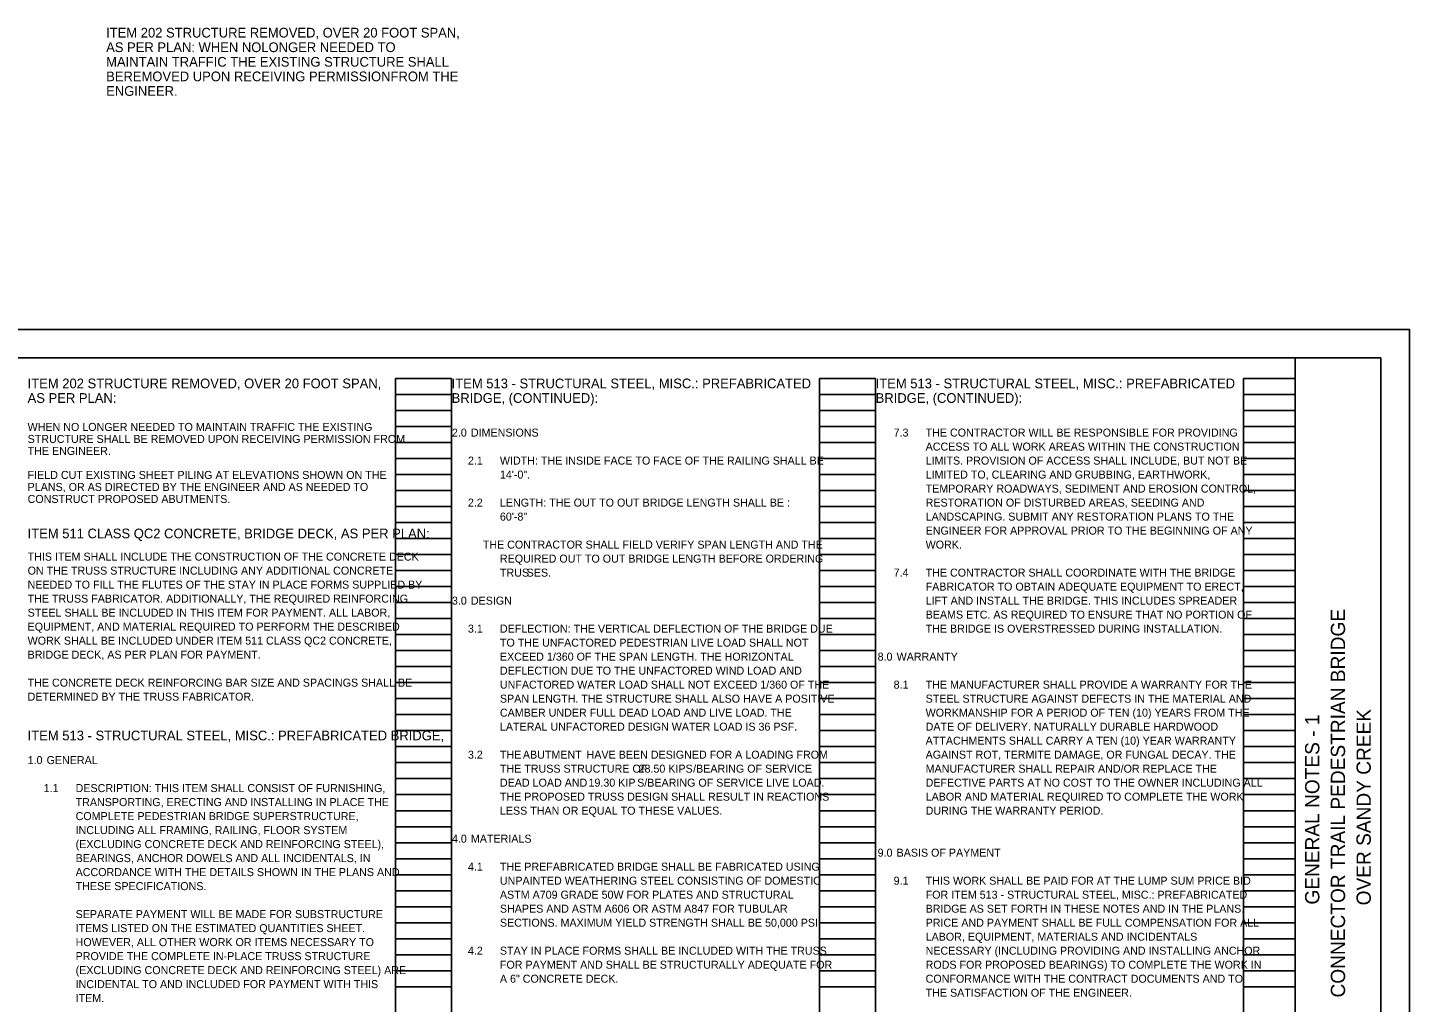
# Model space of a CAD drawing. Extents: x -14.3 to 34, y -8.8 to 27.3.
# Drawn here: x 9.82 to 34, y 10.23 to 27.28 of the extents above; entities that cross this region are included whole.
import ezdxf

# ---------------------------------------------------------------- set-up
doc = ezdxf.new("R2010")
doc.units = 0
for name, color, linetype in [('BR_P_Gen_Text', 7, 'Continuous'), ('SH_Border', 7, 'Continuous'), ('SH_Cut_Line', 7, 'Continuous'), ('SH_Data', 7, 'Continuous'), ('SH_Text', 7, 'Continuous')]:
    doc.layers.add(name, color=color, linetype=linetype)

msp = doc.modelspace()

# ---------------------------------------------------------------- linework, layer by layer
at = {"layer": 'SH_Border'}
msp.add_line((32, 0.5), (32, 21.5), dxfattribs=at)
msp.add_lwpolyline([(1.5, 21.5), (33.5, 21.5), (33.5, 0.5), (1.5, 0.5)], close=True, dxfattribs=at)
at = {"layer": 'SH_Cut_Line'}
msp.add_lwpolyline([(0, 0), (34, 0), (34, 22), (0, 22)], close=True, dxfattribs=at)
at = {"layer": 'SH_Data'}
for p, q in [((16.26, 0.98), (16.26, 21.14)), ((16.26, 21.14), (17.24, 21.14)), ((17.24, 0.98), (17.24, 21.14)), ((23.68, 0.98), (23.68, 21.14)), ((23.68, 21.14), (24.66, 21.14)), ((24.66, 0.98), (24.66, 21.14)), ((31.1, 0.98), (31.1, 21.14)), ((31.1, 21.14), (32, 21.14)), ((32, 0.98), (32, 21.14)), ((16.26, 20.86), (17.24, 20.86)), ((23.68, 20.86), (24.66, 20.86)), ((31.1, 20.86), (32, 20.86)), ((16.26, 20.58), (17.24, 20.58)), ((23.68, 20.58), (24.66, 20.58)), ((31.1, 20.58), (32, 20.58)), ((16.26, 20.3), (17.24, 20.3)), ((23.68, 20.3), (24.66, 20.3)), ((31.1, 20.3), (32, 20.3)), ((16.26, 20.02), (17.24, 20.02)), ((23.68, 20.02), (24.66, 20.02)), ((31.1, 20.02), (32, 20.02)), ((16.26, 19.74), (17.24, 19.74)), ((23.68, 19.74), (24.66, 19.74)), ((31.1, 19.74), (32, 19.74)), ((16.26, 19.46), (17.24, 19.46)), ((23.68, 19.46), (24.66, 19.46)), ((31.1, 19.46), (32, 19.46)), ((16.26, 19.18), (17.24, 19.18)), ((23.68, 19.18), (24.66, 19.18)), ((31.1, 19.18), (32, 19.18)), ((16.26, 18.9), (17.24, 18.9)), ((23.68, 18.9), (24.66, 18.9)), ((31.1, 18.9), (32, 18.9)), ((16.26, 18.62), (17.24, 18.62)), ((23.68, 18.62), (24.66, 18.62)), ((31.1, 18.62), (32, 18.62)), ((16.26, 18.34), (17.24, 18.34)), ((23.68, 18.34), (24.66, 18.34)), ((31.1, 18.34), (32, 18.34)), ((16.26, 18.06), (17.24, 18.06)), ((23.68, 18.06), (24.66, 18.06)), ((31.1, 18.06), (32, 18.06)), ((16.26, 17.78), (17.24, 17.78)), ((23.68, 17.78), (24.66, 17.78)), ((31.1, 17.78), (32, 17.78)), ((16.26, 17.5), (17.24, 17.5)), ((23.68, 17.5), (24.66, 17.5)), ((31.1, 17.5), (32, 17.5)), ((16.26, 17.22), (17.24, 17.22)), ((23.68, 17.22), (24.66, 17.22)), ((31.1, 17.22), (32, 17.22)), ((16.26, 16.94), (17.24, 16.94)), ((23.68, 16.94), (24.66, 16.94)), ((31.1, 16.94), (32, 16.94)), ((16.26, 16.66), (17.24, 16.66)), ((23.68, 16.66), (24.66, 16.66)), ((31.1, 16.66), (32, 16.66)), ((16.26, 16.38), (17.24, 16.38)), ((23.68, 16.38), (24.66, 16.38)), ((31.1, 16.38), (32, 16.38)), ((16.26, 16.1), (17.24, 16.1)), ((23.68, 16.1), (24.66, 16.1)), ((31.1, 16.1), (32, 16.1)), ((16.26, 15.82), (17.24, 15.82)), ((23.68, 15.82), (24.66, 15.82)), ((31.1, 15.82), (32, 15.82)), ((16.26, 15.54), (17.24, 15.54)), ((23.68, 15.54), (24.66, 15.54)), ((31.1, 15.54), (32, 15.54)), ((16.26, 15.26), (17.24, 15.26)), ((23.68, 15.26), (24.66, 15.26)), ((31.1, 15.26), (32, 15.26)), ((16.26, 14.98), (17.24, 14.98)), ((23.68, 14.98), (24.66, 14.98)), ((31.1, 14.98), (32, 14.98)), ((16.26, 14.7), (17.24, 14.7)), ((23.68, 14.7), (24.66, 14.7)), ((31.1, 14.7), (32, 14.7)), ((16.26, 14.42), (17.24, 14.42)), ((23.68, 14.42), (24.66, 14.42)), ((31.1, 14.42), (32, 14.42)), ((16.26, 14.14), (17.24, 14.14)), ((23.68, 14.14), (24.66, 14.14)), ((31.1, 14.14), (32, 14.14)), ((16.26, 13.86), (17.24, 13.86)), ((23.68, 13.86), (24.66, 13.86)), ((31.1, 13.86), (32, 13.86)), ((16.26, 13.58), (17.24, 13.58)), ((23.68, 13.58), (24.66, 13.58)), ((31.1, 13.58), (32, 13.58)), ((16.26, 13.3), (17.24, 13.3)), ((23.68, 13.3), (24.66, 13.3)), ((31.1, 13.3), (32, 13.3)), ((16.26, 13.02), (17.24, 13.02)), ((23.68, 13.02), (24.66, 13.02)), ((31.1, 13.02), (32, 13.02)), ((16.26, 12.74), (17.24, 12.74)), ((23.68, 12.74), (24.66, 12.74)), ((31.1, 12.74), (32, 12.74)), ((16.26, 12.46), (17.24, 12.46)), ((23.68, 12.46), (24.66, 12.46)), ((31.1, 12.46), (32, 12.46)), ((16.26, 12.18), (17.24, 12.18)), ((23.68, 12.18), (24.66, 12.18)), ((31.1, 12.18), (32, 12.18)), ((16.26, 11.9), (17.24, 11.9)), ((23.68, 11.9), (24.66, 11.9)), ((31.1, 11.9), (32, 11.9)), ((16.26, 11.62), (17.24, 11.62)), ((23.68, 11.62), (24.66, 11.62)), ((31.1, 11.62), (32, 11.62)), ((16.26, 11.34), (17.24, 11.34)), ((23.68, 11.34), (24.66, 11.34)), ((31.1, 11.34), (32, 11.34)), ((16.26, 11.06), (17.24, 11.06)), ((23.68, 11.06), (24.66, 11.06)), ((31.1, 11.06), (32, 11.06)), ((16.26, 10.78), (17.24, 10.78)), ((23.68, 10.78), (24.66, 10.78)), ((31.1, 10.78), (32, 10.78)), ((16.26, 10.5), (17.24, 10.5)), ((23.68, 10.5), (24.66, 10.5)), ((31.1, 10.5), (32, 10.5))]:
    msp.add_line(p, q, dxfattribs=at)

# ---------------------------------------------------------------- texts
at = {"layer": 'BR_P_Gen_Text'}
for s, height, p in [('ITEM 202 STRUCTURE REMOVED, OVER 20 FOOT SPAN, ', 0.17, (11.194, 27.107)), ('AS PER PLAN: WHEN NOLONGER NEEDED TO ', 0.17, (11.194, 26.852)), ('MAINTAIN TRAFFIC THE EXISTING STRUCTURE SHALL ', 0.17, (11.194, 26.597)), ('BEREMOVED UPON RECEIVING PERMISSIONFROM THE ', 0.17, (11.194, 26.342)), ('ENGINEER.', 0.17, (11.194, 26.087)), ('ITEM 202 STRUCTURE REMOVED, OVER 20 FOOT SPAN, ', 0.17, (9.82, 20.97)), ('AS PER PLAN: ', 0.17, (9.82, 20.715)), ('WHEN NO LONGER NEEDED TO MAINTAIN TRAFFIC THE EXISTING ', 0.14, (9.82, 20.224)), ('STRUCTURE SHALL BE REMOVED UPON RECEIVING PERMISSION FROM ', 0.14, (9.82, 20.014)), ('THE ENGINEER.', 0.14, (9.82, 19.804)), ('FIELD CUT EXISTING SHEET PILING AT ELEVATIONS SHOWN ON THE ', 0.14, (9.82, 19.384)), ('CONSTRUCT PROPOSED ABUTMENTS.', 0.14, (9.82, 18.964)), ('PLANS, OR AS DIRECTED BY THE ENGINEER AND AS NEEDED TO ', 0.14, (9.82, 19.174))]:
    msp.add_text(s, height=height, dxfattribs=at).set_placement(p)
at = {"layer": 'SH_Data'}
for s, p in [('CONNECTOR TRAIL PEDESTRIAN BRIDGE', (32.875, 10.311)), ('GENERAL NOTES - 1', (32.425, 11.937)), ('OVER SANDY CREEK', (33.325, 11.923))]:
    msp.add_text(s, height=0.25, rotation=90, dxfattribs=at).set_placement(p)
at = {"layer": 'SH_Text'}
for s, height, p in [('ITEM 513 - STRUCTURAL STEEL, MISC.: PREFABRICATED ', 0.17, (17.24, 20.97)), ('ITEM 513 - STRUCTURAL STEEL, MISC.: PREFABRICATED ', 0.17, (24.66, 20.97)), ('BRIDGE, (CONTINUED):', 0.17, (17.24, 20.715)), ('BRIDGE, (CONTINUED):', 0.17, (24.66, 20.715)), ('2.0', 0.14, (17.245, 20.125)), (' DIMENSIONS', 0.14, (17.525, 20.125)), ('7.3', 0.14, (24.975, 20.125)), ('THE CONTRACTOR WILL BE RESPONSIBLE FOR PROVIDING ', 0.14, (25.535, 20.125)), ('ACCESS TO ALL WORK AREAS WITHIN THE CONSTRUCTION ', 0.14, (25.535, 19.88)), ('2.1', 0.14, (17.525, 19.635)), ('WIDTH: THE INSIDE FACE TO FACE OF THE RAILING SHALL BE ', 0.14, (18.085, 19.635)), ('LIMITS. PROVISION OF ACCESS SHALL INCLUDE, BUT NOT BE ', 0.14, (25.535, 19.635)), ('14\'-0".', 0.14, (18.085, 19.39)), ('LIMITED TO, CLEARING AND GRUBBING, EARTHWORK, ', 0.14, (25.535, 19.39)), ('TEMPORARY ROADWAYS, SEDIMENT AND EROSION CONTROL, ', 0.14, (25.535, 19.145)), ('2.2', 0.14, (17.525, 18.9)), ('LENGTH: THE OUT TO OUT BRIDGE LENGTH SHALL BE :', 0.14, (18.085, 18.9)), ('RESTORATION OF DISTURBED AREAS, SEEDING AND ', 0.14, (25.535, 18.9)), ('60\'-8"', 0.14, (18.085, 18.655)), ('LANDSCAPING. SUBMIT ANY RESTORATION PLANS TO THE ', 0.14, (25.535, 18.655)), ('ITEM 511 CLASS QC2 CONCRETE, BRIDGE DECK, AS PER PLAN:', 0.17, (9.82, 18.345)), ('ENGINEER FOR APPROVAL PRIOR TO THE BEGINNING OF ANY ', 0.14, (25.535, 18.41)), ('     THE CONTRACTOR SHALL FIELD VERIFY SPAN LENGTH AND THE ', 0.14, (17.525, 18.165)), ('WORK.', 0.14, (25.535, 18.165)), ('THIS ITEM SHALL INCLUDE THE CONSTRUCTION OF THE CONCRETE DECK ', 0.14, (9.82, 17.955)), ('REQUIRED OUT TO OUT BRIDGE LENGTH BEFORE ORDERING ', 0.14, (18.085, 17.92)), ('ON THE TRUSS STRUCTURE INCLUDING ANY ADDITIONAL CONCRETE ', 0.14, (9.82, 17.71)), ('TRUS', 0.14, (18.085, 17.675)), ('SES.', 0.14, (18.553, 17.675)), ('7.4', 0.14, (24.975, 17.675)), ('THE CONTRACTOR SHALL COORDINATE WITH THE BRIDGE ', 0.14, (25.535, 17.675)), ('NEEDED TO FILL THE FLUTES OF THE STAY IN PLACE FORMS SUPPLIED BY ', 0.14, (9.82, 17.465)), ('FABRICATOR TO OBTAIN ADEQUATE EQUIPMENT TO ERECT, ', 0.14, (25.535, 17.43)), ('THE TRUSS FABRICATOR. ADDITIONALLY, THE REQUIRED REINFORCING ', 0.14, (9.82, 17.22)), ('3.0', 0.14, (17.245, 17.185)), (' DESIGN', 0.14, (17.525, 17.185)), ('LIFT AND INSTALL THE BRIDGE. THIS INCLUDES SPREADER ', 0.14, (25.535, 17.185)), ('STEEL SHALL BE INCLUDED IN THIS ITEM FOR PAYMENT. ALL LABOR, ', 0.14, (9.82, 16.975)), ('BEAMS ETC. AS REQUIRED TO ENSURE THAT NO PORTION OF ', 0.14, (25.535, 16.94)), ('EQUIPMENT, AND MATERIAL REQUIRED TO PERFORM THE DESCRIBED ', 0.14, (9.82, 16.73)), ('3.1', 0.14, (17.525, 16.695)), ('DEFLECTION: THE VERTICAL DEFLECTION OF THE BRIDGE DUE ', 0.14, (18.085, 16.695)), ('THE BRIDGE IS OVERSTRESSED DURING INSTALLATION.', 0.14, (25.535, 16.695)), ('WORK SHALL BE INCLUDED UNDER ITEM 511 CLASS QC2 CONCRETE, ', 0.14, (9.82, 16.485)), ('TO THE UNFACTORED PEDESTRIAN LIVE LOAD SHALL NOT ', 0.14, (18.085, 16.45)), ('BRIDGE DECK, AS PER PLAN FOR PAYMENT.', 0.14, (9.82, 16.24)), ('EXCEED 1/360 OF THE SPAN LENGTH. THE HORIZONTAL ', 0.14, (18.085, 16.205)), ('8.0', 0.14, (24.695, 16.205)), (' WARRANTY', 0.14, (24.975, 16.205)), ('DEFLECTION DUE TO THE UNFACTORED WIND LOAD AND ', 0.14, (18.085, 15.96)), ('THE CONCRETE DECK REINFORCING BAR SIZE AND SPACINGS SHALL BE ', 0.14, (9.82, 15.75)), ('UNFACTORED WATER LOAD SHALL NOT EXCEED 1/360 OF THE ', 0.14, (18.085, 15.715)), ('8.1', 0.14, (24.975, 15.715)), ('THE MANUFACTURER SHALL PROVIDE A WARRANTY FOR THE ', 0.14, (25.535, 15.715)), ('DETERMINED BY THE TRUSS FABRICATOR.', 0.14, (9.82, 15.505)), ('SPAN LENGTH. THE STRUCTURE SHALL ALSO HAVE A POSITIVE ', 0.14, (18.085, 15.47)), ('STEEL STRUCTURE AGAINST DEFECTS IN THE MATERIAL AND ', 0.14, (25.535, 15.47)), ('CAMBER UNDER FULL DEAD LOAD AND LIVE LOAD. THE ', 0.14, (18.085, 15.225)), ('WORKMANSHIP FOR A PERIOD OF TEN (10) YEARS FROM THE ', 0.14, (25.535, 15.225)), ('LATERAL UNFACTORED DESIGN WATER LOAD IS 36 PSF.', 0.14, (18.085, 14.98)), ('DATE OF DELIVERY. NATURALLY DURABLE HARDWOOD ', 0.14, (25.535, 14.98)), ('ITEM 513 - STRUCTURAL STEEL, MISC.: PREFABRICATED BRIDGE,', 0.17, (9.82, 14.81)), ('ATTACHMENTS SHALL CARRY A TEN (10) YEAR WARRANTY ', 0.14, (25.535, 14.735)), ('1.0', 0.14, (9.82, 14.395)), (' GENERAL', 0.14, (10.1, 14.395)), ('3.2', 0.14, (17.525, 14.49)), ('THE ', 0.14, (18.085, 14.49)), ('ABUTMENT ', 0.14, (18.487, 14.49)), ('HAVE BEEN DESIGNED FOR A LOADING FROM ', 0.14, (19.602, 14.49)), ('AGAINST ROT, TERMITE DAMAGE, OR FUNGAL DECAY. THE ', 0.14, (25.535, 14.49)), ('THE TRUSS STRUCTURE OF ', 0.14, (18.085, 14.245)), ('28.50 KIPS', 0.14, (20.511, 14.245)), ('/BEARING OF SERVICE ', 0.14, (21.466, 14.245)), ('MANUFACTURER SHALL REPAIR AND/OR REPLACE THE ', 0.14, (25.535, 14.245)), ('1.1', 0.14, (10.1, 13.905)), ('DESCRIPTION: THIS ITEM SHALL CONSIST OF FURNISHING, ', 0.14, (10.66, 13.905)), ('DEAD LOAD AND ', 0.14, (18.085, 14)), ('19.30 KIP', 0.14, (19.635, 14)), ('S/BEARING OF SERVICE LIVE LOAD. ', 0.14, (20.487, 14)), ('DEFECTIVE PARTS AT NO COST TO THE OWNER INCLUDING ALL ', 0.14, (25.535, 14)), ('TRANSPORTING, ERECTING AND INSTALLING IN PLACE THE ', 0.14, (10.66, 13.66)), ('THE PROPOSED TRUSS DESIGN SHALL RESULT IN REACTIONS ', 0.14, (18.085, 13.755)), ('LABOR AND MATERIAL REQUIRED TO COMPLETE THE WORK ', 0.14, (25.535, 13.755)), ('COMPLETE PEDESTRIAN BRIDGE SUPERSTRUCTURE, ', 0.14, (10.66, 13.415)), ('LESS THAN OR EQUAL TO THESE VALUES.', 0.14, (18.085, 13.51)), ('DURING THE WARRANTY PERIOD. ', 0.14, (25.535, 13.51)), ('INCLUDING ALL FRAMING, RAILING, FLOOR SYSTEM ', 0.14, (10.66, 13.17)), ('(EXCLUDING CONCRETE DECK AND REINFORCING STEEL), ', 0.14, (10.66, 12.925)), ('4.0', 0.14, (17.245, 13.02)), (' MATERIALS', 0.14, (17.525, 13.02)), ('BEARINGS, ANCHOR DOWELS AND ALL INCIDENTALS, IN ', 0.14, (10.66, 12.68)), ('9.0', 0.14, (24.695, 12.775)), (' BASIS OF PAYMENT', 0.14, (24.975, 12.775)), ('ACCORDANCE WITH THE DETAILS SHOWN IN THE PLANS AND ', 0.14, (10.66, 12.435)), ('4.1', 0.14, (17.525, 12.53)), ('THE PREFABRICATED BRIDGE SHALL BE FABRICATED USING ', 0.14, (18.085, 12.53)), ('THESE SPECIFICATIONS.', 0.14, (10.66, 12.19)), ('UNPAINTED WEATHERING STEEL CONSISTING OF DOMESTIC ', 0.14, (18.085, 12.285)), ('9.1', 0.14, (24.975, 12.285)), ('THIS WORK SHALL BE PAID FOR AT THE LUMP SUM PRICE BID ', 0.14, (25.535, 12.285)), ('ASTM A709 GRADE 50W FOR PLATES AND STRUCTURAL ', 0.14, (18.085, 12.04)), ('FOR ITEM 513 - STRUCTURAL STEEL, MISC.: PREFABRICATED ', 0.14, (25.535, 12.04)), ('SHAPES AND ASTM A606 OR ASTM A847 FOR TUBULAR ', 0.14, (18.085, 11.795)), ('BRIDGE AS SET FORTH IN THESE NOTES AND IN THE PLANS. ', 0.14, (25.535, 11.795)), ('SEPARATE PAYMENT WILL BE MADE FOR SUBSTRUCTURE ', 0.14, (10.66, 11.7)), ('SECTIONS. MAXIMUM YIELD STRENGTH SHALL BE 50,000 PSI.', 0.14, (18.085, 11.55)), ('PRICE AND PAYMENT SHALL BE FULL COMPENSATION FOR ALL ', 0.14, (25.535, 11.55)), ('ITEMS LISTED ON THE ESTIMATED QUANTITIES SHEET. ', 0.14, (10.66, 11.455)), ('LABOR, EQUIPMENT, MATERIALS AND INCIDENTALS ', 0.14, (25.535, 11.305)), ('HOWEVER, ALL OTHER WORK OR ITEMS NECESSARY TO ', 0.14, (10.66, 11.21)), ('4.2', 0.14, (17.525, 11.06)), ('STAY IN PLACE FORMS SHALL BE INCLUDED WITH THE TRUSS ', 0.14, (18.085, 11.06)), ('NECESSARY (INCLUDING PROVIDING AND INSTALLING ANCHOR ', 0.14, (25.535, 11.06)), ('PROVIDE THE COMPLETE IN-PLACE TRUSS STRUCTURE ', 0.14, (10.66, 10.965)), ('FOR PAYMENT AND SHALL BE STRUCTURALLY ADEQUATE FOR ', 0.14, (18.085, 10.815)), ('RODS FOR PROPOSED BEARINGS) TO COMPLETE THE WORK IN ', 0.14, (25.535, 10.815)), ('(EXCLUDING CONCRETE DECK AND REINFORCING STEEL) ARE ', 0.14, (10.66, 10.72)), ('A 6" CONCRETE DECK.', 0.14, (18.085, 10.57)), ('CONFORMANCE WITH THE CONTRACT DOCUMENTS AND TO ', 0.14, (25.535, 10.57)), ('INCIDENTAL TO AND INCLUDED FOR PAYMENT WITH THIS ', 0.14, (10.66, 10.475)), ('THE SATISFACTION OF THE ENGINEER.', 0.14, (25.535, 10.325)), ('ITEM.', 0.14, (10.66, 10.23))]:
    msp.add_text(s, height=height, dxfattribs=at).set_placement(p)

doc.saveas('drawing.dxf')
